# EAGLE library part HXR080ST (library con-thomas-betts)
THOMAS&BETTS
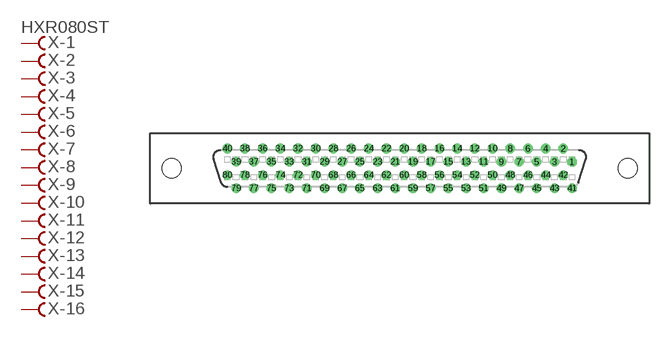
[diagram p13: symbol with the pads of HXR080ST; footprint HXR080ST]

Designator prefix X; gates -1=FV -2=F -3=F -4=F -5=F -6=F -7=F -8=F -9=F -10=F -11=F -12=F -13=F -14=F -15=F -16=F -17=F -18=F -19=F -20=F -21=F -22=F -23=F -24=F -25=F -26=F -27=F -28=F -29=F -30=F -31=F -32=F -33=F -34=F -35=F -36=F -37=F -38=F -39=F -40=F -41=F -42=F -43=F -44=F -45=F -46=F -47=F -48=F -49=F -50=F -51=F -52=F -53=F -54=F -55=F -56=F -57=F -58=F -59=F -60=F -61=F -62=F -63=F -64=F -65=F -66=F -67=F -68=F -69=F -70=F -71=F -72=F -73=F -74=F -75=F -76=F -77=F -78=F -79=F -80=F

## HXR080ST (OC_FARNELL: unknown; OC_NEWARK: unknown)  [HXR080ST]
1  -1:F  pas
2  -2:F  pas
3  -3:F  pas
4  -4:F  pas
5  -5:F  pas
6  -6:F  pas
7  -7:F  pas
8  -8:F  pas
9  -9:F  pas
10  -10:F  pas
11  -11:F  pas
12  -12:F  pas
13  -13:F  pas
14  -14:F  pas
15  -15:F  pas
16  -16:F  pas
17  -17:F  pas
18  -18:F  pas
19  -19:F  pas
20  -20:F  pas
21  -21:F  pas
22  -22:F  pas
23  -23:F  pas
24  -24:F  pas
25  -25:F  pas
26  -26:F  pas
27  -27:F  pas
28  -28:F  pas
29  -29:F  pas
30  -30:F  pas
31  -31:F  pas
32  -32:F  pas
33  -33:F  pas
34  -34:F  pas
35  -35:F  pas
36  -36:F  pas
37  -37:F  pas
38  -38:F  pas
39  -39:F  pas
40  -40:F  pas
41  -41:F  pas
42  -42:F  pas
43  -43:F  pas
44  -44:F  pas
45  -45:F  pas
46  -46:F  pas
47  -47:F  pas
48  -48:F  pas
49  -49:F  pas
50  -50:F  pas
51  -51:F  pas
52  -52:F  pas
53  -53:F  pas
54  -54:F  pas
55  -55:F  pas
56  -56:F  pas
57  -57:F  pas
58  -58:F  pas
59  -59:F  pas
60  -60:F  pas
61  -61:F  pas
62  -62:F  pas
63  -63:F  pas
64  -64:F  pas
65  -65:F  pas
66  -66:F  pas
67  -67:F  pas
68  -68:F  pas
69  -69:F  pas
70  -70:F  pas
71  -71:F  pas
72  -72:F  pas
73  -73:F  pas
74  -74:F  pas
75  -75:F  pas
76  -76:F  pas
77  -77:F  pas
78  -78:F  pas
79  -79:F  pas
80  -80:F  pas

## Footprint HXR080ST (pad centres in mm)
THOMAS&BETTS HFR080ST29xx, HHR080ST29xx
drill 0.864 octagon: 1 24.765,0.953
drill 0.864 round: 2 23.495,2.857; 3 22.225,0.953; 4 20.955,2.857; 5 19.685,0.953; 6 18.415,2.857; 7 17.145,0.953; 8 15.875,2.857; 9 14.605,0.953; 10 13.335,2.857; 11 12.065,0.953; 12 10.795,2.857; 13 9.525,0.953; 14 8.255,2.857; 15 6.985,0.953; 16 5.715,2.857; 17 4.445,0.953; 18 3.175,2.857; 19 1.905,0.953; 20 0.635,2.857; 21 -0.635,0.953; 22 -1.905,2.857; 23 -3.175,0.953; 24 -4.445,2.857; 25 -5.715,0.953; 26 -6.985,2.857; 27 -8.255,0.953; 28 -9.525,2.857; 29 -10.795,0.953; 30 -12.065,2.857; 31 -13.335,0.953; 32 -14.605,2.857; 33 -15.875,0.953; 34 -17.145,2.857; 35 -18.415,0.953; 36 -19.685,2.857; 37 -20.955,0.953; 38 -22.225,2.857; 39 -23.495,0.953; 40 -24.765,2.857; 41 24.765,-2.857; 42 23.495,-0.953; 43 22.225,-2.857; 44 20.955,-0.953; 45 19.685,-2.857; 46 18.415,-0.953; 47 17.145,-2.857; 48 15.875,-0.953; 49 14.605,-2.857; 50 13.335,-0.953; 51 12.065,-2.857; 52 10.795,-0.953; 53 9.525,-2.857; 54 8.255,-0.953; 55 6.985,-2.857; 56 5.715,-0.953; 57 4.445,-2.857; 58 3.175,-0.953; 59 1.905,-2.857; 60 0.635,-0.953; 61 -0.635,-2.857; 62 -1.905,-0.953; 63 -3.175,-2.857; 64 -4.445,-0.953; 65 -5.715,-2.857; 66 -6.985,-0.953; 67 -8.255,-2.857; 68 -9.525,-0.953; 69 -10.795,-2.857; 70 -12.065,-0.953; 71 -13.335,-2.857; 72 -14.605,-0.953; 73 -15.875,-2.857; 74 -17.145,-0.953; 75 -18.415,-2.857; 76 -19.685,-0.953; 77 -20.955,-2.857; 78 -22.225,-0.953; 79 -23.495,-2.857; 80 -24.765,-0.953
hole 2.769 at 32.766,0.013
hole 2.769 at -32.766,0.013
